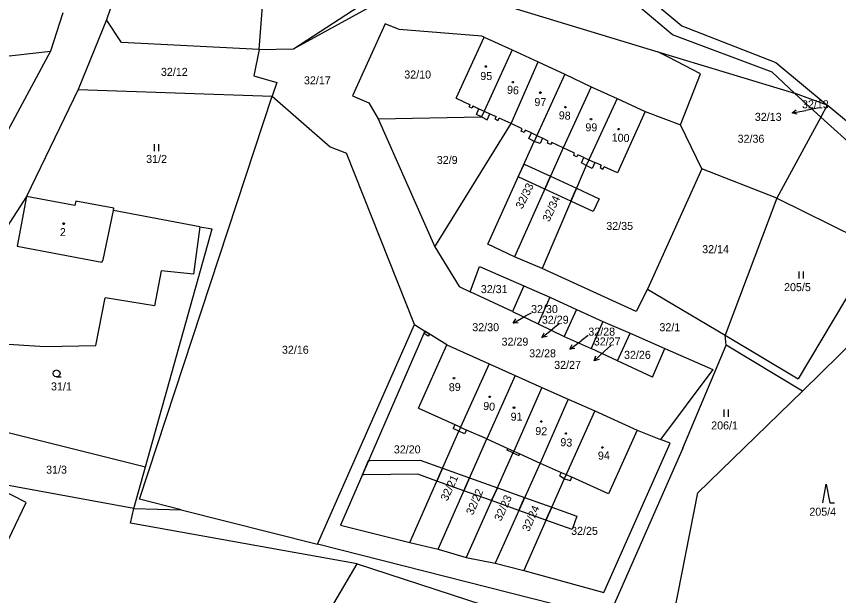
# Model space of a CAD drawing. Extents: x -811039 to -805820, y -1161436 to -1155864.
# Drawn here: x -806560.9 to -806386.2, y -1158211 to -1158088 of the extents above; entities that cross this region are included whole.
import ezdxf

# ---------------------------------------------------------------- set-up
doc = ezdxf.new("R2010")
doc.units = 0
for name, color, linetype in [('Default', 7, 'Continuous'), ('Hranice parcel', 7, 'Continuous'), ('Parcelní čísla', 7, 'Continuous'), ('Pop  PČ popisy', 7, 'Continuous'), ('Vnitřní kresba', 7, 'Continuous'), ('Věcná břemena k části', 7, 'Continuous'), ('Značky budov', 7, 'Continuous'), ('Značky kultur', 7, 'Continuous')]:
    doc.layers.add(name, color=color, linetype=linetype)

# ---------------------------------------------------------------- blocks, each defined once
blk = doc.blocks.new('304')
at = {"layer": 'Default'}
blk.add_lwpolyline([(0, 0), (-0.38, 0.1), (-0.65, 0.37), (-0.75, 0.74), (-0.65, 1.11), (-0.38, 1.38), (-0.01, 1.48), (0.36, 1.38), (0.63, 1.11), (0.73, 0.73), (0.63, 0.35), (0.36, 0.08), (-0.02, -0.02), (0.98, -0.02)], dxfattribs=at)
blk = doc.blocks.new('306')
at = {"layer": 'Default'}
for p, q in [((-0.5, 1.5), (-0.5, 0)), ((0.5, 0), (0.5, 1.5))]:
    blk.add_line(p, q, dxfattribs=at)
blk = doc.blocks.new('308')
at = {"layer": 'Default'}
blk.add_lwpolyline([(-0.75, 0), (0, 4), (0.75, 0), (1.75, 0)], dxfattribs=at)
blk = doc.blocks.new('10292')
at = {"layer": 'Default'}
blk.add_line((0, 3), (0, 0), dxfattribs=at)
blk.add_lwpolyline([(-0.5, 2), (0, 3), (0.5, 2)], dxfattribs=at)
blk = doc.blocks.new('402')
at = {"layer": 'Default'}
blk.add_lwpolyline([(0.09, 0.15), (0.18, 0), (0.09, -0.15), (-0.09, -0.15), (-0.18, 0), (-0.09, 0.15), (0.09, 0.15)], dxfattribs=at)

msp = doc.modelspace()

# ---------------------------------------------------------------- linework, layer by layer
at = {"layer": 'Hranice parcel'}
for p, q in [((-806448.04, -1158066.18), (-806419.5, -1158089.94)), ((-806421.5, -1158091.87), (-806450.67, -1158067.18)), ((-806538.91, -1158080.23), (-806541.73, -1158088.69)), ((-806502.01, -1158094.85), (-806478.06, -1158079.22)), ((-806509.31, -1158095.01), (-806508.21, -1158080.94)), ((-806468.91, -1158082), (-806424.62, -1158095.47)), ((-806502.01, -1158094.85), (-806481.45, -1158083.51)), ((-806551.02, -1158087.22), (-806553.63, -1158095.33)), ((-806541.73, -1158088.69), (-806547.81, -1158103.46)), ((-806538.55, -1158093.51), (-806541.73, -1158088.69)), ((-806482.58, -1158089.54), (-806489.52, -1158104.79)), ((-806479.55, -1158090.73), (-806482.58, -1158089.54)), ((-806461.99, -1158092.15), (-806479.55, -1158090.73)), ((-806419.5, -1158089.94), (-806399.53, -1158097.72)), ((-806467.48, -1158105.31), (-806461.55, -1158092.33)), ((-806461.55, -1158092.33), (-806461.99, -1158092.15)), ((-806461.55, -1158092.33), (-806455.58, -1158095.08)), ((-806400.31, -1158099.79), (-806421.5, -1158091.87)), ((-806509.31, -1158095.01), (-806538.55, -1158093.51)), ((-806509.31, -1158095.01), (-806502.01, -1158094.85)), ((-806578.67, -1158098.14), (-806553.63, -1158095.33)), ((-806553.63, -1158095.33), (-806563.21, -1158113.11)), ((-806509.31, -1158095.01), (-806510.48, -1158100.58)), ((-806455.58, -1158095.08), (-806461.52, -1158108.08)), ((-806455.58, -1158095.08), (-806450.03, -1158097.61)), ((-806424.62, -1158095.47), (-806395.6, -1158104.29)), ((-806422.35, -1158096.64), (-806424.62, -1158095.47)), ((-806455.76, -1158110.73), (-806450.03, -1158097.61)), ((-806450.03, -1158097.61), (-806444.41, -1158100.23)), ((-806415.55, -1158100.16), (-806422.35, -1158096.64)), ((-806399.53, -1158097.72), (-806388.61, -1158106.79)), ((-806395.6, -1158104.29), (-806400.31, -1158099.79)), ((-806510.48, -1158100.58), (-806505.56, -1158102.01)), ((-806444.41, -1158100.23), (-806450.31, -1158113.24)), ((-806444.41, -1158100.23), (-806438.81, -1158102.92)), ((-806419.83, -1158110.97), (-806415.55, -1158100.16)), ((-806547.81, -1158103.46), (-806558.78, -1158126.18)), ((-806547.81, -1158103.46), (-806506.58, -1158104.87)), ((-806505.56, -1158102.01), (-806506.58, -1158104.87)), ((-806438.81, -1158102.92), (-806444.72, -1158115.9)), ((-806438.81, -1158102.92), (-806433.28, -1158105.42)), ((-806534.77, -1158190.5), (-806506.58, -1158104.87)), ((-806506.58, -1158104.87), (-806494.21, -1158115.66)), ((-806489.52, -1158104.79), (-806485.99, -1158106.32)), ((-806467.48, -1158105.31), (-806464.52, -1158106.73)), ((-806388.61, -1158106.79), (-806395.6, -1158104.29)), ((-806395.6, -1158104.29), (-806390, -1158109.34)), ((-806485.99, -1158106.32), (-806484.04, -1158109.7)), ((-806464.73, -1158107.17), (-806464.52, -1158106.73)), ((-806463.89, -1158106.97), (-806464.08, -1158107.46)), ((-806463.89, -1158106.97), (-806462.64, -1158107.56)), ((-806433.28, -1158105.42), (-806439.27, -1158118.43)), ((-806433.28, -1158105.42), (-806427.32, -1158108.14)), ((-806388.61, -1158106.79), (-806390, -1158109.34)), ((-806357.33, -1158133.11), (-806388.61, -1158106.79)), ((-806464.08, -1158107.46), (-806464.73, -1158107.17)), ((-806463.18, -1158108.76), (-806462.64, -1158107.56)), ((-806462.08, -1158109.31), (-806463.18, -1158108.76)), ((-806461.52, -1158108.08), (-806462.08, -1158109.31)), ((-806460.85, -1158109.89), (-806460.29, -1158108.64)), ((-806460.29, -1158108.64), (-806459, -1158109.22)), ((-806427.32, -1158108.14), (-806433.16, -1158121.16)), ((-806427.32, -1158108.14), (-806419.83, -1158110.97)), ((-806484.04, -1158109.7), (-806462.08, -1158109.31)), ((-806484.04, -1158109.7), (-806471.98, -1158136.9)), ((-806462.08, -1158109.31), (-806460.85, -1158109.89)), ((-806459, -1158109.22), (-806459.23, -1158109.72)), ((-806459.23, -1158109.72), (-806458.59, -1158110.05)), ((-806458.59, -1158110.05), (-806458.3, -1158109.55)), ((-806455.76, -1158110.73), (-806458.3, -1158109.55)), ((-806390, -1158109.34), (-806399.36, -1158126.56)), ((-806366.79, -1158130.31), (-806390, -1158109.34)), ((-806471.98, -1158136.9), (-806455.76, -1158110.73)), ((-806453.44, -1158111.82), (-806455.76, -1158110.73)), ((-806453.67, -1158112.33), (-806453.44, -1158111.82)), ((-806452.84, -1158112.1), (-806453.02, -1158112.63)), ((-806451.44, -1158112.7), (-806452.84, -1158112.1)), ((-806415.24, -1158120.34), (-806419.83, -1158110.97)), ((-806453.02, -1158112.63), (-806453.67, -1158112.33)), ((-806452, -1158113.92), (-806451.44, -1158112.7)), ((-806450.88, -1158114.5), (-806452, -1158113.92)), ((-806450.31, -1158113.24), (-806450.88, -1158114.5)), ((-806449.11, -1158113.82), (-806449.63, -1158114.95)), ((-806447.92, -1158114.45), (-806449.11, -1158113.82)), ((-806494.21, -1158115.66), (-806490.8, -1158117.03)), ((-806460.71, -1158136.33), (-806450.88, -1158114.5)), ((-806449.63, -1158114.95), (-806450.88, -1158114.5)), ((-806448.07, -1158114.89), (-806447.92, -1158114.45)), ((-806447.43, -1158115.19), (-806448.07, -1158114.89)), ((-806447.14, -1158114.77), (-806447.43, -1158115.19)), ((-806444.72, -1158115.9), (-806447.14, -1158114.77)), ((-806476.33, -1158153.44), (-806490.8, -1158117.03)), ((-806444.72, -1158115.9), (-806455.06, -1158139)), ((-806442.33, -1158117.02), (-806444.72, -1158115.9)), ((-806442.5, -1158117.47), (-806442.33, -1158117.02)), ((-806441.86, -1158117.78), (-806442.5, -1158117.47)), ((-806441.61, -1158117.36), (-806441.86, -1158117.78)), ((-806440.34, -1158117.95), (-806441.61, -1158117.36)), ((-806440.82, -1158119.06), (-806440.34, -1158117.95)), ((-806439.81, -1158119.59), (-806440.82, -1158119.06)), ((-806439.27, -1158118.43), (-806439.81, -1158119.59)), ((-806437.99, -1158119), (-806438.55, -1158120.25)), ((-806436.69, -1158119.58), (-806437.99, -1158119)), ((-806439.81, -1158119.59), (-806449.18, -1158141.51)), ((-806438.55, -1158120.25), (-806439.81, -1158119.59)), ((-806436.69, -1158119.58), (-806436.9, -1158120.08)), ((-806436.9, -1158120.08), (-806436.27, -1158120.37)), ((-806436.27, -1158120.37), (-806436.02, -1158119.88)), ((-806433.16, -1158121.16), (-806436.02, -1158119.88)), ((-806415.24, -1158120.34), (-806426.84, -1158145.87)), ((-806399.36, -1158126.56), (-806415.24, -1158120.34)), ((-806558.78, -1158126.18), (-806568.02, -1158140.53)), ((-806548.47, -1158128.15), (-806558.78, -1158126.18)), ((-806548.28, -1158127.19), (-806548.47, -1158128.15)), ((-806540.17, -1158128.72), (-806548.28, -1158127.19)), ((-806399.36, -1158126.56), (-806410.31, -1158155.64)), ((-806399.36, -1158126.56), (-806378.19, -1158137.05)), ((-806540.27, -1158129.2), (-806540.17, -1158128.72)), ((-806521.93, -1158132.65), (-806540.27, -1158129.2)), ((-806533.49, -1158183.62), (-806519.3, -1158133.09)), ((-806521.93, -1158132.65), (-806523.28, -1158142.72)), ((-806521.93, -1158132.65), (-806519.3, -1158133.09)), ((-806455.06, -1158139), (-806460.71, -1158136.33)), ((-806471.98, -1158136.9), (-806466.85, -1158145.35)), ((-806378.19, -1158137.05), (-806394.81, -1158164.93)), ((-806449.18, -1158141.51), (-806455.06, -1158139)), ((-806530.13, -1158142), (-806531.56, -1158149.43)), ((-806523.28, -1158142.72), (-806530.13, -1158142)), ((-806464.46, -1158146.47), (-806462.53, -1158141.08)), ((-806462.53, -1158141.08), (-806453.1, -1158145.22)), ((-806429.23, -1158150.61), (-806449.18, -1158141.51)), ((-806366.81, -1158140.98), (-806393.9, -1158167.57)), ((-806466.85, -1158145.35), (-806464.46, -1158146.47)), ((-806453.1, -1158145.22), (-806455.53, -1158150.67)), ((-806453.1, -1158145.22), (-806447.53, -1158147.63)), ((-806455.53, -1158150.67), (-806464.46, -1158146.47)), ((-806426.84, -1158145.87), (-806429.23, -1158150.61)), ((-806426.84, -1158145.87), (-806410.31, -1158155.64)), ((-806544.03, -1158157.86), (-806542.02, -1158147.76)), ((-806531.56, -1158149.43), (-806542.02, -1158147.76)), ((-806447.53, -1158147.63), (-806450.04, -1158153.23)), ((-806447.53, -1158147.63), (-806441.92, -1158150.22)), ((-806455.53, -1158150.67), (-806450.04, -1158153.23)), ((-806441.92, -1158150.22), (-806444.5, -1158155.97)), ((-806441.92, -1158150.22), (-806436.27, -1158152.8)), ((-806496.95, -1158200.1), (-806476.33, -1158153.44)), ((-806476.33, -1158153.44), (-806474.1, -1158154.84)), ((-806450.04, -1158153.23), (-806444.5, -1158155.97)), ((-806436.27, -1158152.8), (-806438.76, -1158158.5)), ((-806436.27, -1158152.8), (-806430.51, -1158155.24)), ((-806474.1, -1158154.84), (-806492.06, -1158196.01)), ((-806469.47, -1158157.74), (-806474.1, -1158154.84)), ((-806444.5, -1158155.97), (-806438.76, -1158158.5)), ((-806433.19, -1158161.11), (-806430.51, -1158155.24)), ((-806430.51, -1158155.24), (-806423.11, -1158158.47)), ((-806410.31, -1158155.64), (-806394.81, -1158164.93)), ((-806410.13, -1158157.79), (-806410.31, -1158155.64)), ((-806565.79, -1158157.41), (-806554.8, -1158158.09)), ((-806554.8, -1158158.09), (-806544.03, -1158157.86)), ((-806475.5, -1158171.21), (-806469.47, -1158157.74)), ((-806469.47, -1158157.74), (-806460.48, -1158161.77)), ((-806433.19, -1158161.11), (-806438.76, -1158158.5)), ((-806425.73, -1158164.6), (-806423.11, -1158158.47)), ((-806423.11, -1158158.47), (-806412.93, -1158162.95)), ((-806419.28, -1158179.7), (-806410.13, -1158157.79)), ((-806393.9, -1158167.57), (-806410.13, -1158157.79)), ((-806425.73, -1158164.6), (-806433.19, -1158161.11)), ((-806460.48, -1158161.77), (-806466.52, -1158175.25)), ((-806460.48, -1158161.77), (-806454.91, -1158164.23)), ((-806412.93, -1158162.95), (-806424.07, -1158177.83)), ((-806454.91, -1158164.23), (-806460.94, -1158177.73)), ((-806454.91, -1158164.23), (-806449.23, -1158166.77)), ((-806449.23, -1158166.77), (-806455.23, -1158180.32)), ((-806449.23, -1158166.77), (-806443.65, -1158169.28)), ((-806393.9, -1158167.57), (-806416.11, -1158189.15)), ((-806443.65, -1158169.28), (-806449.63, -1158182.86)), ((-806443.65, -1158169.28), (-806438.03, -1158171.76)), ((-806475.5, -1158171.21), (-806467.75, -1158174.67)), ((-806438.03, -1158171.76), (-806444.1, -1158185.31)), ((-806438.03, -1158171.76), (-806429.02, -1158175.84)), ((-806467.75, -1158174.67), (-806468.08, -1158175.48)), ((-806566.96, -1158175.3), (-806533.49, -1158183.62)), ((-806477.28, -1158199.72), (-806466.9, -1158176.09)), ((-806466.9, -1158176.09), (-806468.08, -1158175.48)), ((-806466.52, -1158175.25), (-806466.9, -1158176.09)), ((-806465.66, -1158176.63), (-806466.9, -1158176.09)), ((-806465.27, -1158175.85), (-806465.66, -1158176.63)), ((-806460.94, -1158177.73), (-806465.27, -1158175.85)), ((-806429.02, -1158175.84), (-806435.09, -1158189.38)), ((-806429.02, -1158175.84), (-806424.07, -1158177.83)), ((-806471.32, -1158201.12), (-806460.94, -1158177.73)), ((-806460.94, -1158177.73), (-806456.52, -1158179.74)), ((-806436.09, -1158210.34), (-806422.03, -1158178.59)), ((-806422.03, -1158178.59), (-806424.07, -1158177.83)), ((-806456.66, -1158180.14), (-806456.52, -1158179.74)), ((-806455.4, -1158180.7), (-806456.66, -1158180.14)), ((-806455.23, -1158180.32), (-806455.4, -1158180.7)), ((-806419.28, -1158179.7), (-806435.17, -1158215.71)), ((-806455.4, -1158180.7), (-806465.35, -1158202.89)), ((-806455.4, -1158180.7), (-806454.12, -1158181.22)), ((-806454.12, -1158181.22), (-806453.96, -1158180.9)), ((-806453.96, -1158180.9), (-806449.63, -1158182.86)), ((-806535.97, -1158192.47), (-806533.49, -1158183.62)), ((-806449.63, -1158182.86), (-806459.21, -1158204.11)), ((-806449.63, -1158182.86), (-806445.17, -1158184.84)), ((-806445.17, -1158184.84), (-806445.49, -1158185.59)), ((-806444.49, -1158186.17), (-806445.49, -1158185.59)), ((-806444.1, -1158185.31), (-806444.49, -1158186.17)), ((-806535.97, -1158192.47), (-806567.76, -1158186.7)), ((-806558.81, -1158191.24), (-806567.76, -1158186.7)), ((-806444.49, -1158186.17), (-806453.12, -1158205.68)), ((-806444.49, -1158186.17), (-806443.19, -1158186.54)), ((-806443.19, -1158186.54), (-806442.88, -1158185.84)), ((-806435.09, -1158189.38), (-806442.88, -1158185.84)), ((-806422.34, -1158220.82), (-806416.11, -1158189.15)), ((-806525.87, -1158192.81), (-806534.77, -1158190.5)), ((-806570.15, -1158214.79), (-806558.81, -1158191.24)), ((-806536.67, -1158195.62), (-806535.97, -1158192.47)), ((-806535.97, -1158192.47), (-806525.87, -1158192.81)), ((-806525.87, -1158192.81), (-806496.95, -1158200.1)), ((-806488.49, -1158204.22), (-806536.67, -1158195.62)), ((-806492.06, -1158196.01), (-806477.28, -1158199.72)), ((-806435.17, -1158215.71), (-806496.95, -1158200.1)), ((-806477.28, -1158199.72), (-806471.32, -1158201.12)), ((-806471.32, -1158201.12), (-806465.35, -1158202.89)), ((-806465.35, -1158202.89), (-806459.21, -1158204.11)), ((-806509.26, -1158239.64), (-806488.49, -1158204.22)), ((-806488.49, -1158204.22), (-806428.22, -1158223.9)), ((-806459.21, -1158204.11), (-806453.12, -1158205.68)), ((-806453.12, -1158205.68), (-806436.09, -1158210.34))]:
    msp.add_line(p, q, dxfattribs=at)
at = {"layer": 'Pop  PČ popisy'}
for p, q in [((-806390.66, -1158107.47), (-806393.15, -1158107.91)), ((-806451.56, -1158150.98), (-806452.77, -1158151.66)), ((-806445.59, -1158153.24), (-806446.92, -1158154.31)), ((-806439.4, -1158155.77), (-806440.92, -1158156.89)), ((-806434.6, -1158157.86), (-806435.95, -1158159.1))]:
    msp.add_line(p, q, dxfattribs=at)
at = {"layer": 'Vnitřní kresba'}
for p, q in [((-806462.64, -1158107.56), (-806461.52, -1158108.08)), ((-806461.52, -1158108.08), (-806460.29, -1158108.64)), ((-806451.44, -1158112.7), (-806450.31, -1158113.24)), ((-806450.31, -1158113.24), (-806449.11, -1158113.82)), ((-806440.34, -1158117.95), (-806439.27, -1158118.43)), ((-806439.27, -1158118.43), (-806437.99, -1158119)), ((-806558.78, -1158126.18), (-806560.77, -1158136.74)), ((-806542.45, -1158139.7), (-806540.27, -1158129.2)), ((-806560.77, -1158136.74), (-806542.74, -1158140.14)), ((-806542.74, -1158140.14), (-806542.45, -1158139.7)), ((-806467.75, -1158174.67), (-806466.52, -1158175.25)), ((-806466.52, -1158175.25), (-806465.27, -1158175.85)), ((-806456.52, -1158179.74), (-806455.23, -1158180.32)), ((-806455.23, -1158180.32), (-806453.96, -1158180.9)), ((-806445.17, -1158184.84), (-806444.1, -1158185.31)), ((-806444.1, -1158185.31), (-806442.88, -1158185.84))]:
    msp.add_line(p, q, dxfattribs=at)
at = {"layer": 'Věcná břemena k části'}
for p, q in [((-806474.26, -1158155.33), (-806474, -1158154.9)), ((-806473.42, -1158155.86), (-806474.26, -1158155.33)), ((-806474, -1158154.9), (-806473.15, -1158155.44)), ((-806473.15, -1158155.44), (-806473.42, -1158155.86))]:
    msp.add_line(p, q, dxfattribs=at)
for points in [[(-806448.64, -1158124.65), (-806454.28, -1158122.04), (-806453.05, -1158119.32), (-806447.41, -1158121.92)], [(-806443.07, -1158127.22), (-806448.64, -1158124.65), (-806447.41, -1158121.92), (-806441.89, -1158124.47)], [(-806441.89, -1158124.47), (-806437.08, -1158126.69), (-806438.34, -1158129.41), (-806443.07, -1158127.22)], [(-806471.55, -1158186.67), (-806475.6, -1158185.22), (-806487.08, -1158185.33), (-806487.4, -1158185.33), (-806486.09, -1158182.33), (-806485.75, -1158182.33), (-806475.1, -1158182.22), (-806470.34, -1158183.92)], [(-806471.55, -1158186.67), (-806475.6, -1158185.22), (-806487.08, -1158185.33), (-806487.4, -1158185.33), (-806486.09, -1158182.33), (-806485.75, -1158182.33), (-806475.1, -1158182.22), (-806470.34, -1158183.92)], [(-806465.82, -1158188.72), (-806471.55, -1158186.67), (-806470.34, -1158183.92), (-806464.6, -1158185.98)], [(-806459.94, -1158190.83), (-806465.82, -1158188.72), (-806464.6, -1158185.98), (-806458.71, -1158188.09)], [(-806459.94, -1158190.83), (-806458.71, -1158188.09), (-806452.92, -1158190.16), (-806454.16, -1158192.9)], [(-806448.38, -1158194.97), (-806454.16, -1158192.9), (-806452.92, -1158190.16), (-806447.17, -1158192.22)], [(-806447.17, -1158192.22), (-806441.84, -1158194.13), (-806442.85, -1158196.95), (-806448.38, -1158194.97)]]:
    msp.add_lwpolyline(points, close=True, dxfattribs=at)

# ---------------------------------------------------------------- block references
at = {"layer": 'Pop  PČ popisy'}
for p, rotation in [((-806393.15, -1158107.91), 100.09572699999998), ((-806452.77, -1158151.66), 119.347109), ((-806446.92, -1158154.31), 128.9728), ((-806440.92, -1158156.89), 126.509081), ((-806435.95, -1158159.1), 132.754321)]:
    msp.add_blockref('10292', p, dxfattribs=dict(at, rotation=rotation))
at = {"layer": 'Značky budov'}
for p in [(-806461.16, -1158098.61), (-806455.41, -1158101.92), (-806449.57, -1158104.15), (-806444.25, -1158107.21), (-806438.81, -1158109.8), (-806432.97, -1158111.91), (-806550.86, -1158131.99), (-806467.91, -1158164.79), (-806460.36, -1158168.77), (-806455.16, -1158171.07), (-806449.4, -1158174.03), (-806444.16, -1158176.57), (-806436.39, -1158179.54)]:
    msp.add_blockref('402', p, dxfattribs=at)
at = {"layer": 'Značky kultur'}
for name, p in [('306', (-806531.13, -1158116.6)), ('306', (-806394.17, -1158143.62)), ('304', (-806552.37, -1158164.53)), ('306', (-806410.09, -1158173)), ('308', (-806388.84, -1158191.33))]:
    msp.add_blockref(name, p, dxfattribs=at)

# ---------------------------------------------------------------- texts
at = {"layer": 'Parcelní čísla'}
for s, p in [('32/12', (-806530.19, -1158100.58)), ('32/10', (-806478.49, -1158101.14)), ('32/17', (-806499.81, -1158102.38)), ('32/13', (-806393.99, -1158107.47)), ('32/13', (-806404.01, -1158110.14)), ('32/36', (-806407.67, -1158114.79)), ('31/2', (-806533.33, -1158119.08)), ('32/9', (-806471.58, -1158119.3)), ('32/35', (-806435.57, -1158133.31)), ('2', (-806551.67, -1158134.63)), ('32/14', (-806415.19, -1158138.25)), ('32/31', (-806462.23, -1158146.74)), ('205/5', (-806397.8, -1158146.32)), ('32/30', (-806451.55, -1158150.98)), ('32/29', (-806449.26, -1158153.24)), ('32/30', (-806464.04, -1158154.83)), ('32/28', (-806439.39, -1158155.77)), ('32/1', (-806424.28, -1158154.83)), ('32/29', (-806457.82, -1158157.9)), ('32/27', (-806438.23, -1158157.86)), ('32/16', (-806504.48, -1158159.62)), ('32/28', (-806451.95, -1158160.38)), ('32/26', (-806431.8, -1158160.7)), ('32/27', (-806446.64, -1158162.84)), ('31/1', (-806553.55, -1158167.41)), ('206/1', (-806413.28, -1158175.7)), ('32/20', (-806480.71, -1158180.79)), ('31/3', (-806554.59, -1158185.1)), ('205/4', (-806392.42, -1158194.03)), ('32/25', (-806443.04, -1158198.1))]:
    msp.add_text(s, height=1.7, dxfattribs=at).set_placement(p)
for s, rotation, p in [('95', 359.875, (-806462.34, -1158101.46)), ('96', 355.578, (-806456.72, -1158104.35)), ('97', 359.302, (-806450.85, -1158106.99)), ('98', 356.609, (-806445.71, -1158109.78)), ('99', 0.229, (-806440, -1158112.37)), ('100', 357.296, (-806434.46, -1158114.49)), ('32/33', 64.057, (-806453.42, -1158129.01)), ('32/34', 65.546, (-806447.68, -1158131.72)), ('89', 2.807, (-806468.98, -1158167.61)), ('90', 353.973, (-806461.81, -1158171.51)), ('91', 0.974, (-806455.88, -1158173.85)), ('92', 357.927, (-806450.69, -1158176.87)), ('93', 356.38, (-806445.38, -1158179.22)), ('94', 2.464, (-806437.31, -1158182.13)), ('32/21', 65.546, (-806469.34, -1158191.05)), ('32/22', 66.406, (-806463.91, -1158194.02)), ('32/23', 65.718, (-806457.92, -1158195.31)), ('32/24', 66.177, (-806452, -1158197.54))]:
    msp.add_text(s, height=1.7, rotation=rotation, dxfattribs=at).set_placement(p)

doc.saveas('drawing.dxf')
